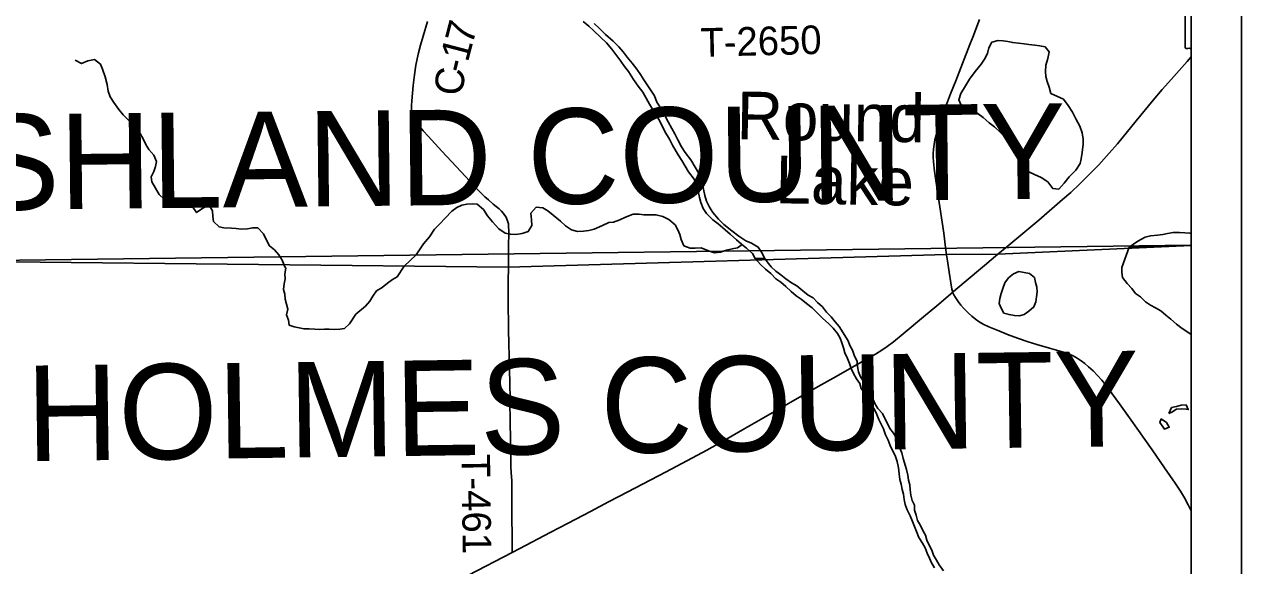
# Model space of a CAD drawing. Extents: x -7.5 to 53.5, y 0 to 22.
# Drawn here: x 6.583 to 9, y 18.553 to 19.628 of the extents above; entities that cross this region are included whole.
import ezdxf

# ---------------------------------------------------------------- set-up
doc = ezdxf.new("R2010")
doc.units = 0
for name, color, linetype in [('GM_X_Corporation', 7, 'Continuous'), ('GM_X_County_Road', 7, 'Continuous'), ('GM_X_County_Road_Text', 7, 'Continuous'), ('GM_X_County_Text', 7, 'Continuous'), ('GM_X_Major_River', 7, 'Continuous'), ('GM_X_Minor_Lake', 7, 'Continuous'), ('GM_X_Minor_River', 7, 'Continuous'), ('GM_X_Minor_River_Text', 7, 'Continuous'), ('GM_X_State_Route', 7, 'Continuous'), ('GM_X_Township_Road', 7, 'Continuous'), ('GM_X_Township_Road_Text', 7, 'Continuous'), ('GM_X_Unincorporated_Location', 7, 'Continuous'), ('SH_Data', 7, 'Continuous')]:
    doc.layers.add(name, color=color, linetype=linetype)

msp = doc.modelspace()

# ---------------------------------------------------------------- linework, layer by layer
at = {"layer": 'GM_X_Corporation'}
for points in [[(4.6087, 14.5302), (4.6021, 15.6139), (4.594, 15.8096), (4.5873, 16.3533), (4.5872, 16.3635), (4.5826, 16.8462), (4.5822, 16.8992), (4.577, 17.1178), (4.5749, 17.2575), (4.5771, 17.6201), (4.5718, 18.1276), (4.5696, 18.2604), (4.5565, 19.1354), (5.0411, 19.1401), (6.0424, 19.1527), (6.0433, 19.1527), (6.5522, 19.1561), (7.544, 19.1455), (8.414, 19.1709), (8.5159, 19.1718), (8.9, 19.1887), (8.9, 20.9), (2.1, 20.9), (2.1, 14.1)], [(8.9, 14.1), (8.9, 19.1887), (8.5159, 19.1718), (8.414, 19.1709), (7.544, 19.1455), (6.5522, 19.1561), (6.0433, 19.1527), (6.0424, 19.1527), (5.0411, 19.1401), (4.5565, 19.1354), (4.5696, 18.2604), (4.5718, 18.1276), (4.5771, 17.6201), (4.5749, 17.2575), (4.577, 17.1178), (4.5822, 16.8992), (4.5826, 16.8462), (4.5872, 16.3635), (4.5873, 16.3533), (4.594, 15.8096), (4.6021, 15.6139), (4.6087, 14.5302)]]:
    msp.add_lwpolyline(points, dxfattribs=at)
at = {"layer": 'GM_X_County_Road'}
msp.add_lwpolyline([(7.5442, 19.1449), (7.5445, 19.1931), (7.545, 19.2079), (7.5449, 19.2178), (7.5446, 19.2262), (7.5441, 19.2319), (7.5426, 19.2375), (7.5413, 19.2412), (7.5396, 19.2449), (7.5374, 19.2485), (7.5348, 19.2524), (7.5307, 19.257), (7.5262, 19.2613), (7.5138, 19.271), (7.5045, 19.2793), (7.4977, 19.2857), (7.4845, 19.2989), (7.4588, 19.3259), (7.4311, 19.3553), (7.4121, 19.3757), (7.3849, 19.4056), (7.3749, 19.4166), (7.3691, 19.4235), (7.3647, 19.4286), (7.3606, 19.4339), (7.3575, 19.4393), (7.355, 19.445), (7.3532, 19.451), (7.3525, 19.454), (7.3518, 19.4602), (7.3517, 19.4665), (7.3526, 19.4758), (7.3554, 19.506), (7.3579, 19.5275), (7.3607, 19.5469), (7.3629, 19.5591), (7.3656, 19.5711), (7.3696, 19.5862), (7.3748, 19.6041), (7.3839, 19.6335)], dxfattribs=at)
at = {"layer": 'GM_X_Major_River'}
msp.add_line((8.0531, 19.1631), (8.0343, 19.1627), dxfattribs=at)
for points in [[(7.6927, 19.6332), (7.7038, 19.6238), (7.7137, 19.6147), (7.727, 19.6022), (7.7388, 19.5909), (7.7498, 19.5784), (7.7574, 19.5678), (7.7677, 19.5546), (7.775, 19.5443), (7.7826, 19.5341), (7.7925, 19.5182), (7.8017, 19.505), (7.8108, 19.4929), (7.8177, 19.4815), (7.8245, 19.469), (7.8345, 19.4527), (7.8429, 19.4387), (7.849, 19.4277), (7.8547, 19.4152), (7.8639, 19.3997), (7.8707, 19.3864), (7.8811, 19.369), (7.8887, 19.3577), (7.8952, 19.3463), (7.902, 19.3353), (7.9131, 19.3202), (7.9181, 19.3088), (7.9208, 19.2967), (7.9235, 19.2842), (7.9262, 19.2743), (7.9311, 19.2622), (7.9376, 19.252), (7.9502, 19.2399), (7.9608, 19.2316), (7.9745, 19.2202), (7.9844, 19.2115), (7.997, 19.2002), (8.0072, 19.1915), (8.0171, 19.1836), (8.0289, 19.173), (8.0343, 19.1627)], [(8.0531, 19.1631), (8.0467, 19.1757), (8.0402, 19.1856), (8.0266, 19.1935), (8.0159, 19.198), (8.0015, 19.2071), (7.9878, 19.2176), (7.9718, 19.2305), (7.9612, 19.2411), (7.9501, 19.2543), (7.9433, 19.2649), (7.9375, 19.277), (7.9341, 19.288), (7.9314, 19.3005), (7.929, 19.3123), (7.9263, 19.3229), (7.9214, 19.3331), (7.9153, 19.3445), (7.9061, 19.3589), (7.8954, 19.3733), (7.8878, 19.3846), (7.8809, 19.3982), (7.8744, 19.4107), (7.8687, 19.4213), (7.8615, 19.4342), (7.8542, 19.4479), (7.8473, 19.46), (7.8389, 19.4732), (7.834, 19.4857), (7.8275, 19.496), (7.813, 19.5175), (7.8065, 19.5281), (7.7989, 19.5387), (7.7897, 19.5505), (7.7802, 19.5626), (7.7722, 19.5732), (7.7634, 19.583), (7.7524, 19.594), (7.7372, 19.6076), (7.7254, 19.6197), (7.7147, 19.6291)], [(8.0343, 19.1627), (8.0531, 19.1631)], [(8.0343, 19.1627), (8.0448, 19.1508), (8.0546, 19.1416), (8.0651, 19.1332), (8.0753, 19.1225), (8.0851, 19.1163), (8.0952, 19.1071), (8.1054, 19.0976), (8.1156, 19.0891), (8.1254, 19.0826), (8.1359, 19.0734), (8.1472, 19.065), (8.1573, 19.055), (8.1682, 19.0439), (8.1799, 19.0343), (8.1889, 19.0248), (8.1979, 19.0144), (8.2028, 19.0049), (8.2065, 18.9954), (8.2098, 18.9855), (8.2124, 18.9756), (8.2172, 18.9646), (8.2217, 18.9547), (8.225, 18.9448), (8.2295, 18.9349), (8.2355, 18.9242), (8.2422, 18.9147), (8.2444, 18.9048), (8.2523, 18.8945), (8.2594, 18.8838), (8.2642, 18.8739), (8.271, 18.8636), (8.2754, 18.8537), (8.2795, 18.8438), (8.2844, 18.8343), (8.2889, 18.8248), (8.2929, 18.813), (8.2985, 18.8027), (8.3022, 18.792), (8.3071, 18.7821), (8.3123, 18.7718), (8.316, 18.7604), (8.3185, 18.7475), (8.3199, 18.7357), (8.3214, 18.7247), (8.3239, 18.7152), (8.3258, 18.7046), (8.3287, 18.6951), (8.3298, 18.6848), (8.332, 18.675), (8.336, 18.6643), (8.3416, 18.6521), (8.3465, 18.6411), (8.3502, 18.6312), (8.3543, 18.6213), (8.3591, 18.6091), (8.3662, 18.598), (8.3714, 18.5885), (8.3755, 18.5782), (8.38, 18.5683)], [(8.058, 19.1561), (8.0531, 19.1631)], [(8.2187, 18.9993), (8.2011, 19.0281), (8.1928, 19.0376), (8.1849, 19.0472), (8.1759, 19.0567), (8.1677, 19.067), (8.1579, 19.0755), (8.1496, 19.085), (8.1391, 19.0901), (8.1285, 19.0985), (8.1172, 19.1085), (8.1063, 19.115), (8.095, 19.1227), (8.0852, 19.1307), (8.0754, 19.1377), (8.0656, 19.1465), (8.058, 19.1561)], [(8.4078, 18.5434), (8.3996, 18.5549), (8.3943, 18.5644), (8.388, 18.5743), (8.385, 18.5842), (8.3798, 18.5941), (8.375, 18.604), (8.372, 18.6139), (8.3668, 18.6235), (8.3623, 18.633), (8.3567, 18.6429), (8.3538, 18.6535), (8.3508, 18.6634), (8.3505, 18.6733), (8.346, 18.6828), (8.3435, 18.6931), (8.342, 18.7037), (8.341, 18.7136), (8.3388, 18.7234), (8.3374, 18.7329), (8.3348, 18.7443), (8.3282, 18.7664), (8.3252, 18.7774), (8.3215, 18.7869), (8.3189, 18.7968), (8.3145, 18.8063), (8.3089, 18.8162), (8.3014, 18.8258), (8.2969, 18.8353), (8.2917, 18.8452), (8.2868, 18.8555), (8.2774, 18.8651), (8.2715, 18.875), (8.267, 18.8868), (8.2607, 18.8986), (8.2554, 18.9089), (8.2495, 18.9188), (8.2435, 18.9283), (8.2394, 18.9378), (8.2372, 18.9485), (8.2365, 18.9583), (8.2309, 18.9713), (8.2276, 18.9808), (8.2224, 18.9903), (8.2187, 18.9993)], [(8.38, 18.5683), (8.3844, 18.5588), (8.3904, 18.5489)]]:
    msp.add_lwpolyline(points, dxfattribs=at)
at = {"layer": 'GM_X_Minor_Lake'}
msp.add_line((8.7766, 19.1857), (8.9, 19.1896), dxfattribs=at)
msp.add_line((8.7766, 19.1857), (8.9, 19.1896), dxfattribs=at)
for points in [[(8.6214, 19.4902), (8.618, 19.5027), (8.6138, 19.5141), (8.6114, 19.5243), (8.6103, 19.5342), (8.611, 19.5467), (8.6151, 19.56), (8.6181, 19.5729), (8.6101, 19.5828), (8.5991, 19.585), (8.5892, 19.5861), (8.5778, 19.5876), (8.5683, 19.5891), (8.557, 19.5902), (8.5456, 19.5916), (8.5357, 19.5935), (8.5263, 19.595), (8.5168, 19.5957), (8.5043, 19.5922), (8.4983, 19.5808), (8.4953, 19.5698), (8.4896, 19.5588), (8.4829, 19.5485), (8.4712, 19.5344), (8.4595, 19.5188), (8.4516, 19.5059), (8.4422, 19.4907), (8.4384, 19.4781), (8.4423, 19.4687), (8.454, 19.4638), (8.4635, 19.46), (8.4772, 19.4498), (8.4871, 19.4427), (8.4985, 19.4321), (8.5092, 19.4241), (8.5206, 19.4136), (8.5324, 19.4011), (8.5419, 19.3886), (8.5503, 19.3761), (8.5549, 19.3663), (8.5595, 19.353), (8.5656, 19.3409), (8.5785, 19.3341), (8.5888, 19.33), (8.6017, 19.3236), (8.615, 19.3149), (8.6249, 19.302), (8.637, 19.3005), (8.6476, 19.3127), (8.6574, 19.3249), (8.6706, 19.3382), (8.6792, 19.3512), (8.6811, 19.3607), (8.6833, 19.3732), (8.6855, 19.3899), (8.6855, 19.4001), (8.6835, 19.4127), (8.6786, 19.4255), (8.6705, 19.4403), (8.664, 19.4532), (8.6553, 19.4664), (8.6461, 19.4793)], [(8.6461, 19.4793), (8.6214, 19.4902)], [(8.9, 19.2126), (8.8981, 19.2131), (8.8875, 19.2142), (8.8765, 19.2149), (8.864, 19.2145), (8.853, 19.2129), (8.8432, 19.2106), (8.8329, 19.2094), (8.8193, 19.2082), (8.8083, 19.2052), (8.794, 19.1975), (8.7766, 19.1857)], [(8.9, 19.0119), (8.8931, 19.0165), (8.8822, 19.0242), (8.8705, 19.033), (8.8596, 19.0426), (8.8498, 19.0506), (8.8396, 19.0591), (8.8291, 19.0649), (8.8189, 19.0706), (8.8091, 19.0772), (8.7989, 19.0867), (8.7891, 19.0937), (8.782, 19.1032), (8.7726, 19.1135), (8.7636, 19.1254), (8.7618, 19.1352), (8.7623, 19.1451), (8.7766, 19.1857)], [(8.5575, 19.1375), (8.5469, 19.1326), (8.537, 19.1244), (8.53, 19.1146), (8.5258, 19.1032), (8.5223, 19.0934), (8.5196, 19.0836), (8.5183, 19.0737), (8.5228, 19.0642), (8.528, 19.0547), (8.5382, 19.0516), (8.5488, 19.0496), (8.5587, 19.0491), (8.5682, 19.052)], [(8.5682, 19.052), (8.5777, 19.0584), (8.5873, 19.067), (8.5911, 19.0769), (8.5943, 19.0966), (8.5933, 19.1061), (8.5907, 19.1156), (8.5885, 19.1251), (8.5787, 19.1335), (8.5575, 19.1375)], [(8.8896, 18.8641), (8.8941, 18.8633), (8.8896, 18.8728), (8.8801, 18.8718), (8.8707, 18.8692), (8.8608, 18.867), (8.8554, 18.8557)], [(8.8554, 18.8557), (8.8611, 18.8583), (8.8706, 18.8639), (8.8801, 18.8645), (8.8896, 18.8641)], [(8.8405, 18.8448), (8.8378, 18.8376), (8.8445, 18.8281)], [(8.8445, 18.8281), (8.8468, 18.8243), (8.8563, 18.828), (8.8511, 18.8375), (8.8405, 18.8448)]]:
    msp.add_lwpolyline(points, dxfattribs=at)
at = {"layer": 'GM_X_Minor_River'}
for points in [[(7.1021, 19.1436), (7.1005, 19.1467), (7.0952, 19.1596), (7.0883, 19.1702), (7.0799, 19.1801), (7.0697, 19.188), (7.0647, 19.1982), (7.0582, 19.2122), (7.0468, 19.2236), (7.0366, 19.2239), (7.0263, 19.222), (7.0142, 19.2212), (7.004, 19.2223), (6.9945, 19.223), (6.9793, 19.2241), (6.9698, 19.2256), (6.9588, 19.2361), (6.9576, 19.2464), (6.9568, 19.2574), (6.95, 19.2691), (6.9375, 19.2626), (6.925, 19.2542), (6.9162, 19.2671), (6.9048, 19.2792), (6.8915, 19.2818), (6.8798, 19.2795), (6.8703, 19.2794), (6.8605, 19.2809), (6.8506, 19.29), (6.8433, 19.3029), (6.8361, 19.315), (6.8353, 19.3249), (6.8402, 19.3359), (6.8435, 19.3458), (6.8454, 19.3556), (6.84, 19.3681), (6.8305, 19.3791), (6.8244, 19.3893), (6.819, 19.4007), (6.8129, 19.4109), (6.8019, 19.4253), (6.7905, 19.437), (6.7794, 19.4484), (6.7707, 19.4586), (6.7608, 19.4726), (6.7535, 19.4839), (6.7497, 19.4949), (6.7477, 19.5086), (6.7435, 19.5237), (6.7385, 19.5389), (6.7343, 19.5488), (6.7225, 19.5578), (6.7092, 19.5551), (6.6968, 19.5498), (6.6842, 19.5565)], [(8.0081, 19.1909), (7.9993, 19.1843), (7.9883, 19.182), (7.977, 19.1796), (7.9656, 19.1758), (7.9535, 19.1742), (7.9417, 19.178), (7.9269, 19.1844), (7.9148, 19.1836), (7.9049, 19.1832), (7.8928, 19.1884), (7.8874, 19.2009), (7.8844, 19.2104), (7.8809, 19.2199), (7.8752, 19.2301), (7.8626, 19.2403), (7.8509, 19.2463), (7.8372, 19.2497), (7.8133, 19.2496), (7.8039, 19.2507), (7.7917, 19.2507), (7.7766, 19.2453), (7.7656, 19.2399), (7.7531, 19.235), (7.7433, 19.2342), (7.7308, 19.2284), (7.7145, 19.2212), (7.7036, 19.2185), (7.693, 19.2173), (7.6812, 19.2165), (7.6695, 19.2198), (7.6577, 19.2278), (7.6478, 19.2372), (7.6333, 19.2489), (7.6227, 19.2576), (7.6128, 19.2633), (7.5992, 19.2647), (7.5886, 19.2529), (7.5898, 19.24), (7.591, 19.2283), (7.5838, 19.2169), (7.5717, 19.2123), (7.5592, 19.2103), (7.5482, 19.211), (7.5376, 19.2133), (7.5254, 19.2216), (7.5129, 19.236), (7.503, 19.2477), (7.4946, 19.2602), (7.482, 19.2711), (7.4722, 19.2718), (7.4619, 19.2711), (7.4521, 19.2691), (7.4419, 19.2641), (7.4321, 19.2569), (7.4189, 19.2432), (7.4072, 19.2314), (7.3977, 19.2215), (7.3876, 19.2063), (7.3759, 19.1918), (7.368, 19.1804), (7.3608, 19.1701), (7.3495, 19.1587), (7.337, 19.148)], [(7.337, 19.148), (7.3237, 19.1266), (7.3138, 19.121), (7.3043, 19.1143), (7.2936, 19.1053), (7.2825, 19.0989), (7.2749, 19.0884), (7.2691, 19.0782), (7.2607, 19.0684), (7.2416, 19.0527), (7.2285, 19.0331), (7.219, 19.0241), (7.2095, 19.0226), (7.1993, 19.022), (7.1887, 19.0228), (7.1792, 19.0229), (7.1697, 19.0222), (7.1598, 19.0227), (7.1485, 19.0232), (7.1386, 19.0233), (7.1288, 19.0256), (7.1189, 19.0272), (7.1087, 19.0307), (7.1077, 19.0406), (7.1036, 19.0513), (7.106, 19.0626), (7.1034, 19.0725), (7.1012, 19.0824), (7.1005, 19.0919), (7.098, 19.1014), (7.0988, 19.1124), (7.1012, 19.1226), (7.1001, 19.1328), (7.1021, 19.1436)]]:
    msp.add_lwpolyline(points, dxfattribs=at)
at = {"layer": 'GM_X_State_Route'}
for points in [[(8.4142, 19.1704), (8.4121, 19.1847), (8.4086, 19.2134), (8.4007, 19.2656), (8.3929, 19.3179), (8.3903, 19.3363), (8.3884, 19.3549), (8.3877, 19.3643), (8.3876, 19.3705), (8.3882, 19.3799), (8.3894, 19.3892), (8.391, 19.3984), (8.3932, 19.4075), (8.3966, 19.4195), (8.4035, 19.4401), (8.4121, 19.4634), (8.4222, 19.4895), (8.4325, 19.5155), (8.4459, 19.5503), (8.4604, 19.588), (8.4661, 19.6025), (8.4798, 19.6372)], [(8.5161, 19.1713), (8.5341, 19.1862), (8.5618, 19.2095), (8.5976, 19.2393), (8.6446, 19.2799), (8.6609, 19.2943), (8.679, 19.3113), (8.6989, 19.3309), (8.7162, 19.3488), (8.7371, 19.3718), (8.7533, 19.3906), (8.7906, 19.4363), (8.824, 19.4771), (8.8421, 19.4984), (8.8545, 19.5123), (8.8916, 19.5541), (8.9, 19.5633)], [(8.4264, 19.0962), (8.4248, 19.1023), (8.4225, 19.1145), (8.4191, 19.1359), (8.4159, 19.1583), (8.4142, 19.1704)], [(8.4264, 19.0962), (8.4278, 19.0973), (8.4492, 19.1153), (8.4896, 19.1493), (8.5161, 19.1713)], [(7.4648, 18.5344), (7.5516, 18.5794), (7.5669, 18.5873), (7.6273, 18.6192), (7.6631, 18.6379), (7.7071, 18.6611), (7.743, 18.6798), (7.7816, 18.6998), (7.8559, 18.7387), (7.8998, 18.762), (7.9381, 18.7827), (7.976, 18.8039), (8.0138, 18.8256), (8.0461, 18.8441), (8.1593, 18.9088), (8.189, 18.9257), (8.2133, 18.9395), (8.2539, 18.9624), (8.2728, 18.9732), (8.2859, 18.9814), (8.2961, 18.9884), (8.3085, 18.9977), (8.3278, 19.0135), (8.3683, 19.0473), (8.3947, 19.0691), (8.4264, 19.0962)], [(8.9, 18.6623), (8.8941, 18.6743), (8.8866, 18.688), (8.8785, 18.7013), (8.8683, 18.7169), (8.8471, 18.7476), (8.8221, 18.7832), (8.8079, 18.8036), (8.7955, 18.8214), (8.7776, 18.8468), (8.7576, 18.8744), (8.743, 18.8945), (8.7299, 18.912), (8.7221, 18.9216), (8.7138, 18.9309), (8.705, 18.9398), (8.6959, 18.9483), (8.6888, 18.9544), (8.6812, 18.9602), (8.6736, 18.9652), (8.6652, 18.9697), (8.6564, 18.9735), (8.648, 18.9765), (8.6321, 18.9811), (8.6182, 18.985), (8.5936, 18.9921), (8.5762, 18.9973), (8.5552, 19.0047), (8.5354, 19.0122), (8.5182, 19.0192), (8.4982, 19.0277), (8.4871, 19.033), (8.4791, 19.0376), (8.4714, 19.0428), (8.4642, 19.0485), (8.4574, 19.0548), (8.4487, 19.0636), (8.4426, 19.0706), (8.4369, 19.0779), (8.4316, 19.0855), (8.4285, 19.0908), (8.4273, 19.0935), (8.4264, 19.0962)]]:
    msp.add_lwpolyline(points, dxfattribs=at)
at = {"layer": 'GM_X_Township_Road'}
msp.add_lwpolyline([(7.5516, 18.5794), (7.5516, 18.5868), (7.5516, 18.6104), (7.5512, 18.6508), (7.551, 18.6726), (7.551, 18.7068), (7.551, 18.7223), (7.55, 18.7378), (7.5493, 18.7502), (7.549, 18.7688), (7.5488, 18.7811), (7.5485, 18.8028), (7.5483, 18.8151), (7.548, 18.8273), (7.5478, 18.8304), (7.5478, 18.8487), (7.5474, 18.8702), (7.5475, 18.8763), (7.547, 18.9228), (7.5466, 18.9353), (7.5459, 18.9632), (7.5457, 18.9692), (7.5456, 18.9723), (7.5452, 18.9909), (7.545, 19.0002), (7.5447, 19.0157), (7.5445, 19.028), (7.5442, 19.0435), (7.544, 19.059), (7.5437, 19.0869), (7.5438, 19.1055), (7.544, 19.124), (7.5441, 19.1395), (7.5442, 19.1449)], dxfattribs=at)
at = {"layer": 'GM_X_Unincorporated_Location'}
msp.add_line((8.8877, 19.7833), (8.8877, 19.5832), dxfattribs=at)
msp.add_lwpolyline([(8.9, 19.5791), (8.9, 19.7868), (8.8902, 19.7868)], dxfattribs=at)
for centre, radius, start, end in [((8.8907, 19.5828), 0.00308, 171.4911, 258.3065), ((8.8912, 19.6033), 0.0235, 267.339, 280.6039), ((8.896, 19.5717), 0.00848, 61.7382, 93.2717)]:
    msp.add_arc(centre, radius, start, end, dxfattribs=at)
at = {"layer": 'SH_Data'}
for p, q in [((9, 21), (9, 14)), ((8.9, 20.9), (8.9, 14.1))]:
    msp.add_line(p, q, dxfattribs=at)
msp.add_lwpolyline([(8.9, 19.1896), (4.5566, 19.1336), (4.6149, 14.11), (4.6151, 14.1)], dxfattribs=at)

# ---------------------------------------------------------------- texts
at = {"layer": 'GM_X_County_Road_Text'}
for s, rotation, p in [('7', 75.4023, (7.4726, 19.5849)), ('1', 75.3264, (7.4637, 19.551)), ('-', 76.2061, (7.4582, 19.5286)), ('C', 82.3391, (7.4523, 19.4839))]:
    msp.add_text(s, height=0.0568, rotation=rotation, dxfattribs=at).set_placement(p)
at = {"layer": 'GM_X_County_Text'}
for s, rotation, p in [('ASHLAND COUNTY', 0.605, (6.3159, 19.2572)), ('HOLMES COUNTY', 0.7747, (6.5883, 18.7608))]:
    msp.add_text(s, height=0.189394, rotation=rotation, dxfattribs=at).set_placement(p)
at = {"layer": 'GM_X_Minor_River_Text'}
for s, p in [('Round', (7.997, 19.3999)), ('Lake', (8.0739, 19.2727))]:
    msp.add_text(s, height=0.09471, rotation=358.9928, dxfattribs=at).set_placement(p)
at = {"layer": 'GM_X_Township_Road_Text'}
for s, rotation, p in [('T-2650', 1.4034, (7.926, 19.5632)), ('T-461', 270.7998, (7.4509, 18.7746))]:
    msp.add_text(s, height=0.05682, rotation=rotation, dxfattribs=at).set_placement(p)

doc.saveas('drawing.dxf')
